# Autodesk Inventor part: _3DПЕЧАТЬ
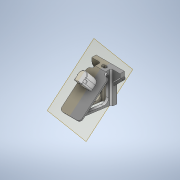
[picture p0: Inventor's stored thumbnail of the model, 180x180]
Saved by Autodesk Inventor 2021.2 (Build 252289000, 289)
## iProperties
Created: 2025-12
Part Number: _3DПЕЧАТЬ
Material: Типовые
Document SubType Name: Modeling
Designer: BR
Density: 1 g/cm^3
Appearance: По умолчанию
Author: BR
Part Number: link_50R
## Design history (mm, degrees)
derived "подбор угла.iam"
node "РабПлоскость1"
sketch "Эскиз1"
  geometry: L1 (5.3, 104.073)-(5.3, 114.073) reference; L2 (5.3, 0)-(5.3, 104.073) reference; L3 (19.441, 130.925)-(5.3, 114.073) reference; L4 (23.272, 127.712)-(11.781, 137.353) reference; L5 (42.235, 111.799)-(23.272, 127.712) reference; L6 (93.926, 68.425)-(42.235, 111.799) reference; L7 (5.3, -10)-(5.3, 0) reference; L8 (93.926, 68.425)-(5.3, -10); L9 (5.3, 104.073)-(5.3, 0) reference; L10 (5.3, -10)-(5.3, 0); 1 further point
  constraints: 4 end point, 1 collinear
extrude "Выдавливание1" join sketch "Эскиз1" stored distance "d1" = 35; taper "d2" = 0 deg
sketch "Эскиз2"
  geometry: L1 (5.3, 0)-(5.3, 104.073) reference; L2 (5.3, 104.073)-(5.3, 114.073) reference; L3 (23.272, 127.712)-(11.781, 137.353) reference; L4 (42.235, 111.799)-(23.272, 127.712) reference; L5 (93.926, 68.425)-(42.235, 111.799) reference; L6 (93.926, 68.425)-(5.3, -10) reference; L7 (-2.36, 120.5)-(5.3, 114.073) reference; L8 (11.781, 137.353)-(-2.36, 120.5) reference; L9 (5.3, -10)-(5.3, 0) reference; L10 (13.8, 104.073)-(13.8, 8.872); L11 (13.8, 8.872)-(80.907, 68.254); L12 (80.907, 68.254)-(36.771, 105.288); L13 (36.771, 105.288)-(17.808, 121.2); L14 (17.808, 121.2)-(12.829, 125.378); L15 (12.829, 125.378)-(9.615, 121.548); L16 (9.615, 121.548)-(13.8, 118.036); L17 (13.8, 118.036)-(13.8, 104.073); 1 further point
  constraints: 16 end point, 7 other
  dimensions: "d3" = 8.5 distance between parallel lines of L1 L10
extrude "Выдавливание2" cut sketch "Эскиз2" stored distance "d4" = 49.5; taper "d5" = 0 deg
sketch "Эскиз3"
  geometry: L1 (93.926, 68.425)-(5.3, -10) reference; L2 (11.781, 137.353)-(93.926, 68.425) reference; L3 (5.3, -10)-(5.3, 114.073) reference; L4 (5.3, 114.073)-(-2.36, 120.5) reference; L5 (11.781, 137.353)-(-2.36, 120.5) reference; L6 (13.8, 118.036)-(13.8, 8.872) reference; L7 (13.8, 8.872)-(80.907, 68.254) reference; L8 (80.907, 68.254)-(12.829, 125.378) reference; L9 (12.829, 125.378)-(9.615, 121.548) reference; L10 (9.615, 121.548)-(13.8, 118.036) reference; L11 (93.926, 68.425)-(11.781, 137.353) reference; L12 (93.926, 68.425)-(5.3, -10) reference; L13 (5.3, 114.073)-(5.3, -10) reference; L14 (-2.36, 120.5)-(5.3, 114.073) reference; L15 (11.781, 137.353)-(-2.36, 120.5) reference; 1 further point
extrude "Выдавливание3" cut sketch "Эскиз3" stored distance "d6" = 17; taper "d7" = 0 deg
fillet "Сопряжение1" dims "d10" = 4.75
fillet "Сопряжение3" dims "d12" = 2.75
fillet "Сопряжение5" dims "d14" = 6.75
fillet "Сопряжение6" dims "d15" = 14.25
mirror "Зеркальное отражение2"
sketch "Эскиз10"
  geometry: L1 (41.125, 13.8)-(32.125, 13.8) reference; L2 (32.125, -2.36)-(32.125, 5.3) reference; L3 (32.125, 5.3)-(41.125, 5.3) reference; L4 (41.125, 5.3)-(41.125, -2.36) reference; L5 (41.125, -2.36)-(32.125, -2.36) reference; L6 (47.25, 0)-(0, 0) reference; L7 (41.125, 0)-(32.125, 0); L8 (15.125, 5.3)-(15.125, -2.36) reference; L9 (15.125, -2.36)-(6.125, -2.36) reference; L10 (6.125, -2.36)-(6.125, 5.3) reference; L11 (6.125, 5.3)-(15.125, 5.3) reference; 1 further point
  constraints: 4 point on line, 2 end point
extrude "Выдавливание10" join sketch "Эскиз10" stored distance "d27" = 35; taper "d28" = 0 deg
sketch "Эскиз11"
  geometry: L1 (0, 114.073)-(0, 118.52) reference; L2 (0, 116.296)-(-3.364, 116.296); L3 (-3.364, 116.296)-(-3.364, 124.602); L4 (-3.364, 124.602)-(0, 124.602); L5 (0, 124.602)-(0, 116.296); 2 further points
  constraints: 8 end point, 2 parallel, 1 horizontal, 1 midpoint, 1 perpendicular
extrude "Выдавливание11" cut sketch "Эскиз11" distance "d29" = 35; taper "d30" = 0 deg
mirror "Зеркальное отражение5"
sketch "Эскиз12"
  geometry: L1 (0, 5.3)-(0, 0) reference; L2 (17, 0)-(0, 0) reference; L3 (17, 0)-(17, 5.3) reference; L4 (0, 5.3)-(17, 5.3) reference; 1 further point
extrude "Выдавливание12" join sketch "Эскиз12" stored distance "d31" = 35; taper "d32" = 0 deg
fillet "Сопряжение8" dims "d33" = 9
fillet "Сопряжение9" dims "d34" = 2.75
fillet "Сопряжение10" dims "d35" = 5.5
mirror "Зеркальное отражение6"
sketch "Эскиз13"
  geometry: L1 (5.3, -10)-(0, -10) reference; L2 (103.247, 79.533)-(93.926, 68.425) reference; L3 (5.3, -10)-(103.247, 79.533); L4 (103.247, 79.533)-(129.26, 103.312); L5 (129.26, 103.312)-(137.086, 37.423); L6 (131.408, 30.229)-(39.219, -26.576); L7 (39.219, -26.576)-(5.3, -10); A1 r 6.474 centre (130.657, 36.66) between (131.408, 30.229) and (137.086, 37.423); 1 further point
  constraints: 10 end point, 2 point on circle, 1 centre point, 1 point on line, 1 tangent
extrude "Выдавливание13" cut sketch "Эскиз13" stored distance "d36" = 56.25; taper "d37" = 0 deg
node "Твердое тело1"
node "Ryobi_link_30_base1.1.ipt:1" dims "d0" = 10
node "Ryobi_link_30_base2.ipt:1" dims "d0" = 10
node "Спроецированная петля1"
node "Спроецированная петля8"
node "Спроецированная петля9"
